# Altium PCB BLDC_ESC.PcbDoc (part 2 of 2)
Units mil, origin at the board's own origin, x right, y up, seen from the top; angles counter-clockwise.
Board outline 1574.8 x 2362.2 mil, 2 copper layers (Top Layer, Bottom Layer), stack 65.792 mil thick; 131 components, 100 nets, 479 pads, 292 vias.
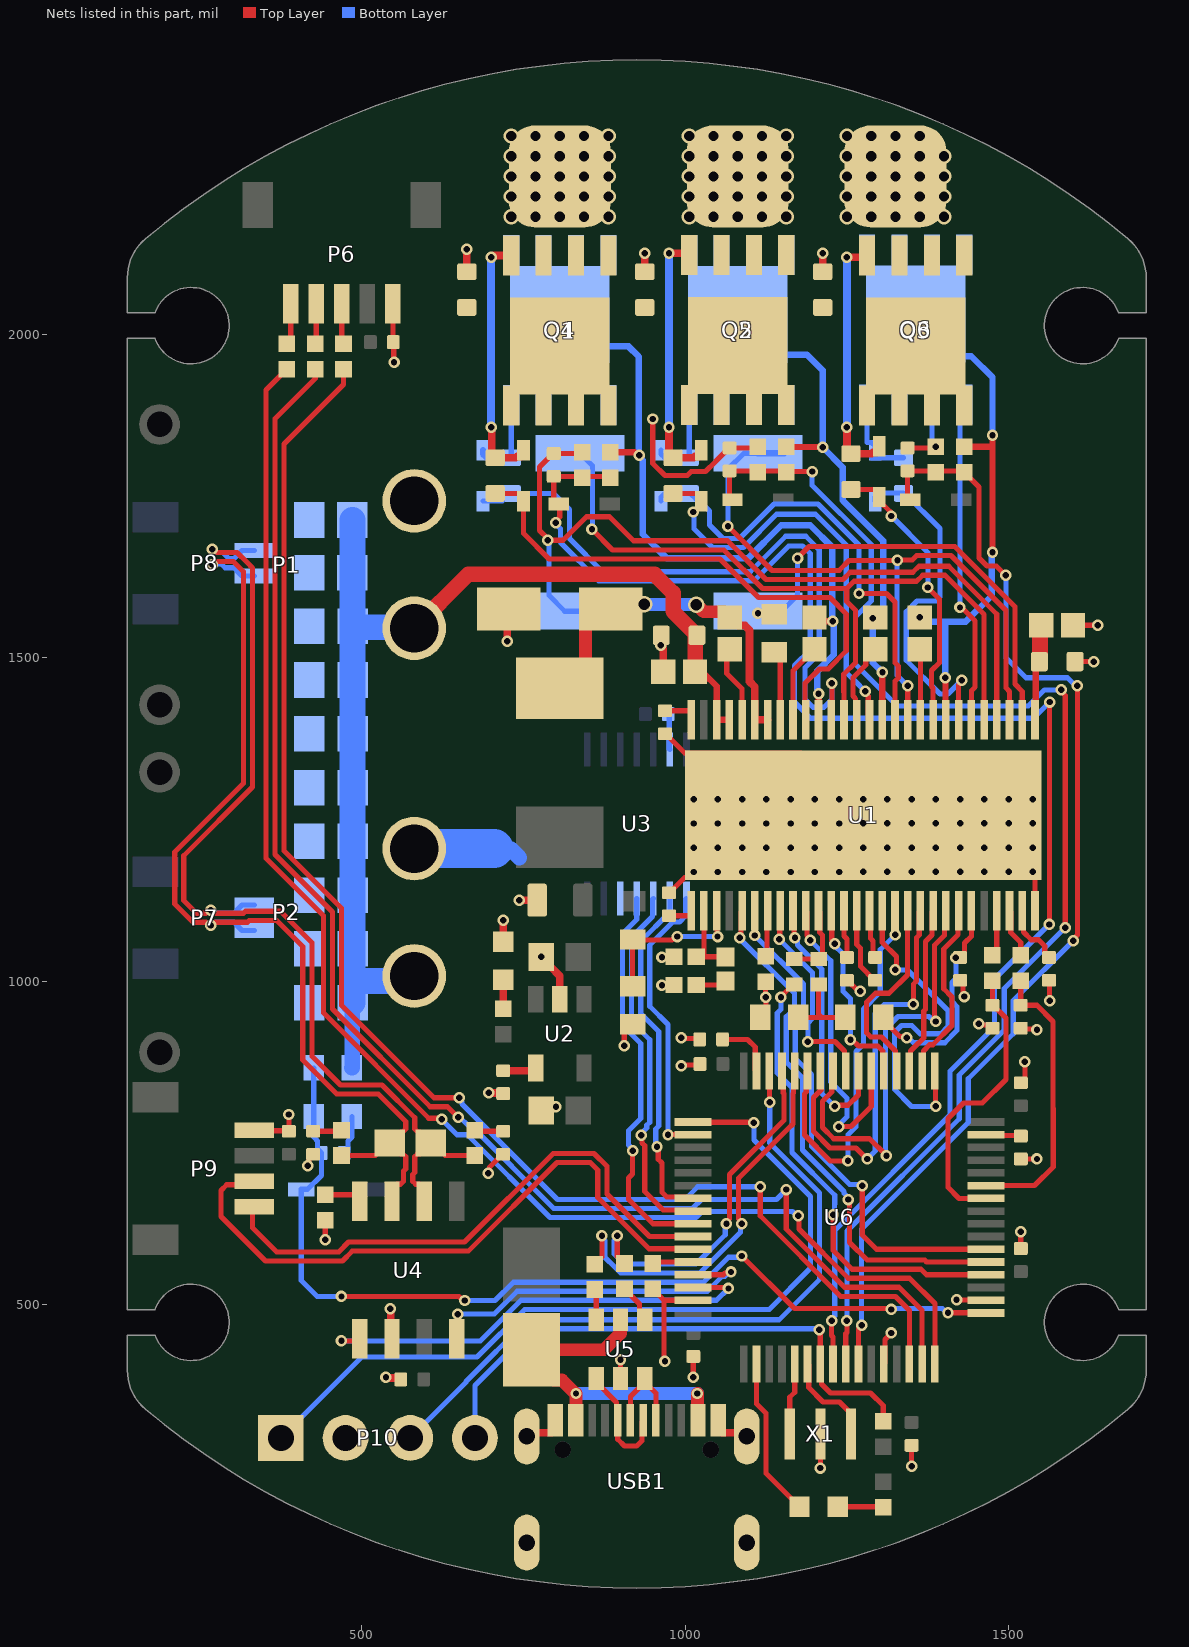
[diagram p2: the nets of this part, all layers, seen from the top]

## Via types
v1: diameter 17.72, hole 9.84, Top Layer to Bottom Layer, tented both sides, 211 vias
v2: diameter 23.62, hole 15.75, Top Layer to Bottom Layer, tented both sides, 74 vias
v3: diameter 25.59, hole 17.72, Top Layer to Bottom Layer, tented both sides, 7 vias

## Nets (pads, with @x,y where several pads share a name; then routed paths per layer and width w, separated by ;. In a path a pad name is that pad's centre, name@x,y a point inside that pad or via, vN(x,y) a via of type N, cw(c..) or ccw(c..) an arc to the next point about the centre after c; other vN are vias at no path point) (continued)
A_SENSE: C36.2 D9.2 R17.1 R25.2 U6.8 | length 2457.5
  Top Layer w8: v1(799.81,1708.56) 799.81,1711.19 806.14,1717.53 806.14,1735.74 D9.2@804.38,1737.5 802.69,1737.5 796.85,1743.34 C36.2@796.85,1780.07 882.38,1780.07 R17.1@884.35,1778.1 ; v1(1226.28,474.89) 1226.28,452.19 1228.44,450.03 U6.8@1228.44,408.19 ; v1(1562.5,1087.5) 1563.01,1088.01 1563.01,1430.74 v1(1563.51,1431.25)
  Bottom Layer w8: v1(799.81,1708.56) 799.81,1706.27 807.06,1699.02 807.06,1678.06 866.37,1618.75 1106.43,1618.75 1160.2,1672.52 1181.49,1672.52 1193.33,1660.68 1193.33,1512.08 1168.75,1487.5 1168.75,1431.25 1193.75,1406.25 1538.51,1406.25 v1(1563.51,1431.25) ; v1(1226.28,474.89) 1226.28,477.52 1231.14,482.38 1231.14,482.81 1231.25,482.92 1231.25,614.6 1409.5,792.85 1409.5,860.55 1478.25,929.3 1478.25,1003.25 v1(1562.5,1087.5)
B_SENSE: C37.2 D10.2 R18.1 R26.2 U6.9 | length 2060.6
  Top Layer w8: D10.2@1073.13,1743.75 1068.75,1748.13 C37.2@1068.75,1788.53 1154.28,1788.53 1155.32,1787.5 v1(1196.26,1787.5) ; U6.9@1248.12,408.19 1248.12,455.12 1250,457 v1(1250,474.89) ; v1(1581.25,1450) 1581.25,1447.37 1587.39,1441.23 v1(1587.39,1082.65)
  Bottom Layer w8: v1(1196.26,1787.5) 1196.26,1766.24 1287.5,1675 1287.5,1587.5 1263.05,1563.05 1263.05,1489.73 1327.78,1425 1530.2,1425 1555.31,1450.11 1581.14,1450.11 v1(1581.25,1450) ; v1(1250,474.89) 1250,613.55 1423.5,787.05 1423.5,854.75 1493.22,924.47 1493.22,988.37 1587.39,1082.55 v1(1587.39,1082.65)
BOOT0: R38.1 U6.60 | length 62.8
  Top Layer w8: R38.1@950,563.43 952.24,565.67 U6.60@1011.9,565.67
C_SENSE: C38.2 D11.2 R19.1 R27.2 U6.10 | length 1773.8
  Top Layer w8: U6.10@1267.81,408.19 1267.81,463.03 1272.75,467.98 v1(1272.75,468.2) ; D11.2@1348.13,1743.75 1343.75,1748.13 C38.2@1343.75,1788.53 1387.5,1788.53 1429.28,1788.53 1454.14,1763.67 1454.14,1653.86 1466.36,1641.64 1480.85,1641.64 1495.5,1626.99 v1(1495.69,1626.99) ; v1(1600,1062.5) 1600,1065.13 1606.25,1071.38 v1(1606.25,1456.25)
  Bottom Layer w8: v1(1272.75,468.2) 1272.75,616.5 1437.5,781.25 1437.5,848.95 1507.22,918.67 1507.22,969.72 v1(1600,1062.5) ; v1(1495.69,1626.99) 1495.69,1499.73 1526.56,1468.86 1591.01,1468.86 1603.62,1456.25 v1(1606.25,1456.25)
CAN1_N: P7.2 P8.2 R32.1 R33.1 U4.6 | length 1630.7
  Top Layer w8: v1(268.75,1667.47) 271.38,1667.47 276.24,1662.61 307.19,1662.61 323.05,1646.75 331.25,1638.55 331.25,1300 225,1193.75 225,1124.66 244.87,1104.79 259.19,1104.79 264.05,1109.65 v1(266.68,1109.65) 269.31,1109.65 274.16,1104.79 317.46,1104.79 320.41,1107.75 374.55,1107.75 423.01,1059.29 423.01,883.63 467.25,839.38 531.25,839.38 582,788.63 582,771.52 586.69,766.83 589.71,766.83 R32.1@606.54,750 ; U4.6@596.85,659.4 596.85,678.1 589.04,685.91 583.54,685.91 578.85,690.6 578.85,700.69 582,703.84 582,728.48 586.69,733.17 589.71,733.17 R32.1@606.54,750 ; R33.1@675,730.32 629.13,730.32 609.45,750 R32.1@606.54,750
  Bottom Layer w8: v1(266.68,1109.65) 269.31,1109.65 274.16,1104.79 285.41,1104.79 285.5,1104.88 302.61,1104.88 307.3,1109.57 307.3,1109.76 315.11,1117.57 P7.2@333.81,1117.57 ; v1(268.75,1667.47) 271.38,1667.47 276.24,1662.61 285.19,1662.61 294.93,1652.87 302.61,1652.87 307.3,1657.55 307.3,1657.74 315.11,1665.55 P8.2@333.81,1665.55
CAN1_P: P7.1 P8.1 R31.1 R32.2 U4.7 | length 1610.5
  Top Layer w8: v1(268.75,1643.75) 271.38,1643.75 276.24,1648.61 301.39,1648.61 317.25,1632.75 317.25,1305.8 211,1199.55 211,1118.86 239.07,1090.79 259.19,1090.79 264.05,1085.94 v1(266.68,1085.94) 269.31,1085.94 274.16,1090.79 323.25,1090.79 326.21,1093.75 368.75,1093.75 409.01,1053.49 409.01,877.83 413.11,873.73 461.45,825.38 525.45,825.38 568,782.83 568,771.52 563.31,766.83 560.29,766.83 R32.2@543.46,750 ; R31.1@468.75,730.32 520.87,730.32 540.55,750 R32.2@543.46,750 ; U4.7@546.85,659.4 546.85,678.1 554.66,685.91 560.16,685.91 564.85,690.6 564.85,706.49 568,709.64 568,728.48 563.31,733.17 560.29,733.17 R32.2@543.46,750
  Bottom Layer w8: v1(266.68,1085.94) 269.31,1085.94 274.16,1090.79 291.21,1090.79 291.3,1090.88 302.61,1090.88 307.3,1086.2 307.3,1086.01 315.11,1078.2 P7.1@333.81,1078.2 ; v1(268.75,1643.75) 269.75,1644.75 283.25,1644.75 289.13,1638.87 302.61,1638.87 307.3,1634.18 307.3,1633.99 315.11,1626.18 P8.1@333.81,1626.18
CAN1_RX: U4.4 U6.61 | length 549.1
  Top Layer w8: U4.4@646.85,446.8 648.43,448.38 v1(648.43,485.21) ; U6.61@1011.9,545.99 1059.08,545.99 1061.6,548.51 1068.93,548.51 v1(1070.79,550.37)
  Bottom Layer w8: v1(648.43,485.21) 705.01,485.21 740.3,520.5 1034.05,520.5 1057.22,543.67 1061.46,543.67 1068.16,550.37 v1(1070.79,550.37)
CAN1_TX: U4.1 U6.62 | length 716.7
  Top Layer w8: v1(468.75,443.75) 493.8,443.75 U4.1@496.85,446.8 ; U6.62@1011.9,526.3 1065.39,526.3 v1(1066.89,524.81)
  Bottom Layer w8: v1(468.75,443.75) 683.35,443.75 746.1,506.5 1048.58,506.5 v1(1066.89,524.81)
DC_CAL: U1.12 U6.37 | length 300.3
  Top Layer w8: U1.12@1225.79,1108.61 1226.61,1107.79 1226.61,1063.66 1230.96,1059.31 v1(1230.96,1057.49) ; v1(1255.45,909.21) 1258.07,909.21 1267.78,899.5 1297.53,899.5 1305.27,891.76 1305.27,862.86 U6.37@1307.18,860.95
  Bottom Layer w8: v1(1230.96,1057.49) 1230.96,1054.86 1243.75,1042.07 1243.75,984.22 1255.45,972.53 v1(1255.45,909.21)
EN_GATE: U1.16 U6.33 | length 548.9
  Top Layer w8: U1.16@1304.53,1108.61 1304.53,1059.77 1326.55,1037.75 ; v1(1324.67,1017.26) 1326.53,1019.12 1326.53,1037.72 ; U6.33@1385.92,860.95 1386.71,860.16 1386.71,807.04 v1(1387.5,806.25)
  Bottom Layer w8: v1(1324.67,1017.26) 1343.57,1017.26 1406.36,954.47 1406.36,929.69 1395.31,918.64 1363.04,918.64 1350.32,931.36 1334.59,931.36 1323.54,920.31 1323.54,832.71 1350,806.25 v1(1387.5,806.25)
GAIN: U1.10 U6.38 | length 482.8
  Top Layer w8: U1.10@1186.42,1108.61 1188.32,1106.71 1188.32,1070.56 1193.25,1065.64 v1(1193.25,1063.01) ; v1(1237.5,775) 1256.25,775 1287.49,806.24 U6.38@1287.49,860.95
  Bottom Layer w8: v1(1193.25,1063.01) 1225,1031.25 1225,843.75 1250,818.75 1250,790.13 1237.5,777.63 v1(1237.5,775)
GH_A: D3.1 R14.1 U1.47 | length 851.1
  Top Layer w8: R14.1@706.25,1753.69 744.09,1753.69 750,1747.79 D3.1@750,1741.88 750,1692.08 789.62,1652.46 1053.79,1652.46 1113.47,1592.78 1176.3,1592.78 ; 1176.33,1592.81 1223.67,1592.81 1249.05,1567.43 1249.05,1510.4 1221.18,1482.53 1207.53,1482.53 1185.24,1460.24 1185.24,1405.06 U1.47@1186.42,1403.89
GH_B: D4.1 R15.1 U1.42 | length 674.7
  Top Layer w8: R15.1@981.25,1753.69 1019.09,1753.69 1025,1747.79 1025,1735.97 1014.03,1725 v1(1012.5,1725) ; v1(1278.33,1447.77) 1278.33,1445.15 1282.94,1440.54 1282.94,1405.79 U1.42@1284.84,1403.89
  Bottom Layer w8: v1(1012.5,1725) 1013.43,1724.07 1013.43,1699.07 1042.31,1670.19 1089.99,1670.19 1141.3,1721.5 1201.4,1721.5 1249.05,1673.85 1249.05,1477.06 1263.33,1462.78 v1(1278.33,1447.77)
GH_C: D5.1 R16.1 U1.37 | length 441.5
  Top Layer w8: R16.1@1256.25,1759.94 1294.09,1759.94 1300,1754.04 1300,1742.22 1316.89,1725.33 1316.89,1720.61 v1(1318.75,1718.75) ; v1(1374.89,1608.36) 1393.2,1590.05 1393.2,1492.05 1380.92,1479.77 1380.92,1455.08 1383.27,1452.74 U1.37@1383.27,1403.89
  Bottom Layer w8: v1(1318.75,1718.75) 1375.46,1662.04 1375.46,1608.92 v1(1374.89,1608.36)
GL_A: D6.1 R20.1 U1.45 | length 988
  Top Layer w8: U1.45@1225.79,1403.89 1226.96,1405.06 1226.96,1459.54 v1(1226.29,1460.21)
  Bottom Layer w8: D6.1@687.5,1741.88 R20.1@717.48,1741.88 ; R20.1@731.25,1753.69 796.31,1753.69 821.06,1728.94 821.06,1683.86 872.17,1632.75 1100.63,1632.75 1155.38,1687.5 1186.31,1687.5 1207.33,1666.48 1207.33,1506.26 1185.24,1484.17 1185.24,1435.47 1197.46,1423.25 1214.74,1423.25 1226.96,1435.47 1226.96,1459.54 v1(1226.29,1460.21)
GL_B: D7.1 R21.1 U1.40 | length 726.8
  Top Layer w8: v1(1268.64,1599.04) 1311.19,1599.04 1324.45,1585.78 1324.45,1492.05 1329.44,1487.06 1329.44,1468.61 1324.21,1463.38 U1.40@1324.21,1403.89
  Bottom Layer w8: D7.1@962.5,1741.88 962.5,1747.79 968.41,1753.69 1008.21,1753.69 1017.21,1744.69 1019.48,1744.69 1037.5,1726.67 1037.5,1705.03 1058.34,1684.19 1084.19,1684.19 1137.5,1737.5 1205.2,1737.5 1268.64,1674.06 v1(1268.64,1599.04)
GL_C: D8.1 R22.1 U1.35 | length 552.6
  Top Layer w8: U1.35@1422.64,1403.89 1422.64,1457.51 1427.29,1462.16 v1(1427.29,1464.79)
  Bottom Layer w8: D8.1@1293.75,1741.88 1293.75,1747.79 1300.45,1754.48 1336.71,1754.48 R22.1@1337.5,1753.69 1339.46,1753.69 1393.75,1699.4 1393.75,1593.54 1387.71,1587.5 1358.4,1587.5 1341.64,1570.75 1341.64,1495.86 1393.75,1443.75 1406.25,1443.75 v1(1427.29,1464.79)
GND: C1.1 C2.1 C3.2 C4.2 C5.2 C8.2 C10.2 C13.2 C14.2 C15.2 C16.2 C17.2 C18.2 C19.1 C20.1 C21.1 C22.1 C23.1 C24.1 C25.1 C26.1 C27.1 C28.1 C29.1 C30.1 C31.1 C32.1 C33.2 C34.2 C35.2 C36.1 C37.1 C38.1 C39.1 C40.1 C41.1 C42.1 C43.1 C44.1 C45.1 C46.1 C47.1 C48.1 C49.1 C50.1 C51.1 D1.2 DS1.2 P1.2 P2.2 P6.1 P9.1 P10.2 Q6.1 Q6.2 Q6.3 R3.1 R4.1 R5.2 R6.2 R8.1 R13.2 R23.2 R24.2 R25.1 R26.1 R27.1 R34.1 R38.2 U1.28 U1.30 U1.32 U1.34 U1.EXP U2.2 U3.5 U3.13 U4.2 U5.2 U6.12 U6.18 U6.63 USB1.1 USB1.12 USB1.A USB1.B USB1.C USB1.D X1.2 | length 5943.8
  Top Layer w8: P9.1@333.81,769.29 334.6,768.5 386.71,768.5 C44.1@387.5,767.72 v1(387.5,793.75) ; v1(416.46,714.79) 418.32,716.65 418.32,726.44 424.17,732.28 C41.1@425,732.28 ; v1(443.75,600.11) R34.1@443.75,630.32 ; P6.1@547.83,2046.9 548.4,2046.33 548.4,1988.07 C39.1@548.97,1987.5 549.48,1986.98 549.48,1956.77 v1(550,1956.25) ; v1(695.75,703.08) 697.61,704.94 697.61,712.13 717.77,732.28 C42.1@718.75,732.28 ; R25.1@840.6,1817.47 838.63,1815.5 C36.1@796.85,1815.5 795.87,1815.5 775,1794.64 775,1696.38 787.5,1683.88 v1(787.5,1681.25) 810.99,1681.25 847.39,1717.66 883.03,1717.66 920.22,1680.46 1065.38,1680.46 1125.07,1620.78 1164.7,1620.78 ; U5.2@900,385.97 v1(900,414.64) ; v1(905.73,900) 905.73,921.22 906.65,922.15 907.92,922.15 R4.1@918.75,932.97 ; R38.2@950,524.06 967.44,506.62 ; v1(950,1868.75) 950,1799.86 968.61,1781.25 1003.12,1781.25 1009.38,1787.5 1031.61,1787.5 1046.77,1802.66 1046.77,1802.97 1067.77,1823.97 C37.1@1068.75,1823.97 1110.53,1823.97 R26.1@1112.5,1825.93 ; v1(964.11,993.75) C2.1@982.68,993.75 ; v1(964.11,1037.05) 982.22,1037.05 C1.1@982.68,1037.5 ; v1(968.75,412.5) 967.44,413.81 967.44,506.62 ; C3.2@968.75,1382.28 969.73,1382.28 999.37,1352.64 1178.61,1352.64 U1.EXP@1275,1256.25 1178.61,1159.86 1087.96,1159.86 999.37,1159.86 975.98,1136.47 R3.1@975,1136.47 ; v1(993.75,868.75) 995.3,870.3 1021.33,870.3 C47.1@1022.88,871.85 ; v1(993.75,912.5) 995.09,911.16 1021.02,911.16 C46.1@1022.37,909.82 ; U6.63@1011.9,506.62 967.44,506.62 ; v1(1012.5,387.5) C45.1@1012.5,419.78 ; v1(1112.5,1568.75) 1135.78,1568.75 R6.2@1137.5,1567.03 ; R8.1@1115.94,943.75 1125,952.81 v1@1125,975 ; v1(1124.32,974.99) 1124.32,998.68 R5.2@1124.85,999.21 ; 1164.73,1620.81 1243.94,1620.81 1255.03,1631.9 1305.6,1631.9 1305.68,1631.82 1351.89,1631.82 1361.28,1641.21 1407.39,1641.21 1481.69,1566.91 U1.32@1481.69,1403.89 ; v1(1173.68,1653.67) 1191.56,1671.55 1416.66,1671.55 1509.69,1578.51 1509.69,1459.06 1521.06,1447.69 U1.30@1521.06,1403.89 ; v1(1209.02,247.23) X1.2@1209.01,300 ; C10.2@1250,1001.03 1250.98,1001.03 1267.82,984.19 v1(1270.45,984.19) ; v1(1275,1243.75) v1(1312.5,1243.75) v1(1350,1243.75) v1(1387.5,1243.75) v1(1425,1243.75) U1.EXP@1444.35,1243.75 ; U6.12@1307.18,408.19 1309.08,410.1 1309.08,446.09 1318.47,455.48 v1(1318.47,456.05) ; C38.1@1343.75,1823.97 1385.53,1823.97 v1(1387.5,1825.93) ; v1(1350,250) C48.1@1350,282.28 ; v1(1419.41,507.23) 1419.71,506.93 1464.35,506.93 U6.18@1464.66,506.62 ; v1(1424.71,1577.43) 1427.34,1577.43 1448.01,1556.76 1448.01,1454.26 1442.32,1448.57 U1.34@1442.32,1403.89 ; C13.2@1425,1001.03 1429.39,996.65 1429.39,977.91 v1(1431.25,976.05) ; U1.EXP@1444.35,1256.25 1497.18,1203.43 1540.75,1159.86 U1.28@1540.75,1108.61 ; v1(1454.03,934.1) 1455.89,932.24 1469.85,932.24 C17.2@1474.9,927.18 ; C18.2@1518.65,927.18 1519.74,926.09 1542.66,926.09 v1(1543.75,925) ; C51.1@1518.75,586.47 v1(1518.75,612.5) ; C49.1@1518.75,725 v1(1543.75,725) ; C50.1@1518.75,842.72 1519.27,842.72 1525.11,848.56 v1(1525.11,875) ; C14.2@1562.5,1001.03 1562.92,1000.62 1562.92,970 v1(1563.33,969.58) ; C15.2@1599.61,1550 v1(1637.5,1550) ; C16.2@1602.56,1493.75 v1(1631.25,1493.75)
  Top Layer w12: v1(537.5,387.5) 538.59,386.41 558.33,386.41 C43.1@560.38,384.35 ; v1(543.86,493.64) 544.84,492.66 544.84,448.81 U4.2@546.85,446.8 ; C33.2@662.5,2096.31 v1(662.5,2131.25) ; v1(696.55,827.62) 697.35,826.83 717.96,826.83 C32.1@718.75,826.03 ; DS1.2@718.75,1060.78 v1@718.75,1093.75 ; v1(725,1525) 725,1572.49 D1.2@727.51,1575 ; v1(743.75,1125) C8.2@771.21,1125 ; USB1.A@755.12,296.16 760.92,301.96 793.41,301.96 799.22,307.77 USB1.1@799.22,320.96 ; C30.1@777.71,800 783.35,805.64 v1(800.25,805.64) ; C29.1@777.71,1035.53 791.39,1021.85 792.14,1021.85 806.25,1007.73 U2.2@806.25,971.9 ; C34.2@937.5,2096.31 v1(937.5,2125) ; v1(962.5,1518.75) 962.5,1517.2 965.99,1513.71 C4.2@965.99,1478.1 ; C5.2@963.04,1534.35 962.77,1534.08 962.77,1520.03 v1@965.14,1517.66 ; USB1.12@1051.18,320.96 1051.18,307.77 1056.99,301.96 1089.48,301.96 USB1.D@1095.28,296.16 ; C35.2@1212.5,2096.31 v1(1212.5,2125)
  Bottom Layer w8: C31.1@473.08,734.4 478.92,740.24 478.92,753 484.89,758.96 R13.2@484.89,790.65 ; v1(787.5,1681.25) 789.36,1679.39 789.36,1596.25 813.9,1571.7 R23.2@837.5,1571.7 ; C40.1@973.97,1412.5 975.26,1411.21 975.26,1359.03 U3.13@976.38,1357.91 ; R24.2@1112.5,1571.7 1149.14,1571.7 1173.68,1596.25 v1(1173.68,1653.67) ; Q6.2@1381.25,1891.1 1381.25,1834.81 1387.5,1828.56 v1(1387.5,1825.93) ; v1(1424.71,1577.43) 1424.71,1884.56 Q6.1@1431.25,1891.1
  Bottom Layer w24: 729.69,1204.68 743.75,1190.62
  Bottom Layer w60: P2.2@581.25,1204.68 704.68,1204.68
  other v1: 777.71,1037.5 718.75,1093.75 1012.96,1168.49 1050.46,1168.49 1087.96,1168.49 1125.46,1168.49 1162.96,1168.49 1200.46,1168.49 1237.96,1168.49 1275,1168.75 1312.5,1168.75 1350,1168.75 1387.5,1168.75 1425,1168.75 1462.5,1168.75 1500,1168.75 1537.5,1168.75 1012.96,1205.99 1050.46,1205.99 1087.96,1205.99 1125.46,1205.99 1162.96,1205.99 1200.46,1205.99 1237.96,1205.99 1275,1206.25 1312.5,1206.25 1350,1206.25 1387.5,1206.25 1425,1206.25 1462.5,1206.25 1500,1206.25 1537.5,1206.25 1012.96,1243.49 1050.46,1243.49 1087.96,1243.49 1125.46,1243.49 1162.96,1243.49 1200.46,1243.49 1237.96,1243.49 1462.5,1243.75 1500,1243.75 1537.5,1243.75 1012.96,1280.99 1050.46,1280.99 1087.96,1280.99 1125.46,1280.99 1162.96,1280.99 1200.46,1280.99 1237.96,1280.99 1275,1281.25 1312.5,1281.25 1350,1281.25 1387.5,1281.25 1425,1281.25 1462.5,1281.25 1500,1281.25 1537.5,1281.25
HAL_A: R28.2 U6.14 | length 2259.8
  Top Layer w8: R28.2@471.9,1945.96 471.9,1921.9 380,1830 380,1201.25 468.75,1112.5 468.75,962.5 611.67,819.58 v1(650.83,819.58) ; v1(1115.98,682.01) 1115.98,637.13 1240.49,512.61 1324.92,512.61 1346.55,490.99 U6.14@1346.55,408.19
  Bottom Layer w8: v1(650.83,819.58) 650.83,816.96 654.92,812.87 654.92,810.18 802.6,662.5 1000,662.5 1019.51,682.01 v1(1115.98,682.01)
HAL_B: R29.2 U6.15 | length 2299.1
  Top Layer w8: R29.2@428.15,1945.96 428.15,1931.25 366,1869.1 366,1195.45 454.75,1106.7 454.75,956.7 605.87,805.58 632.84,805.58 v1(649.05,789.38) ; v1(1156.25,677.74) 1156.14,677.64 1156.14,616.76 1246.29,526.61 1330.72,526.61 1366.23,491.1 U6.15@1366.23,408.19
  Bottom Layer w8: v1(649.05,789.38) 651.68,789.38 664.56,776.5 668.8,776.5 796.8,648.5 1011,648.5 1025,662.5 1141.01,662.5 v1(1156.25,677.74)
HAL_C: R30.2 U6.16 | length 2289.3
  Top Layer w8: R30.2@384.4,1945.96 352,1913.56 352,1189.65 440.75,1100.9 440.75,950.9 603.65,788 621.78,788 v1(623.64,786.14) ; v1(1175,637.5) 1176.06,636.44 1176.06,616.64 1252.09,540.61 1346.89,540.61 1385.92,501.58 U6.16@1385.92,408.19
  Bottom Layer w8: v1(623.64,786.14) 647.28,762.5 663,762.5 791,634.5 1016.8,634.5 1026.16,643.86 1166.01,643.86 1172.37,637.5 v1(1175,637.5)
INH_A: U1.17 U6.43 | length 601.9
  Top Layer w8: U6.43@1189.07,860.95 1187.16,859.05 1187.16,828.54 1184.28,825.66 1184.28,761.95 1224.25,721.99 v1(1251.57,721.99) ; U1.17@1324.21,1108.61 1324.44,1108.38 1324.44,1071.75 v1(1324.67,1071.52)
  Bottom Layer w8: v1(1251.57,721.99) 1251.57,762.4 1264,774.83 1264,891.09 1275.75,902.84 1275.75,957 1301.43,982.68 1301.43,1048.28 v1(1324.67,1071.52)
INH_B: U1.19 U6.42 | length 643.7
  Top Layer w8: U6.42@1208.75,860.95 1210.65,859.05 1210.65,832.23 1198.28,819.86 1198.28,767.75 1223.89,742.14 1264.11,742.14 v1(1281.25,725) ; v1(1352.67,964.22) 1352.67,995.05 1357.53,999.91 1357.53,1066.92 1361.68,1071.07 1361.68,1106.71 U1.19@1363.58,1108.61
  Bottom Layer w8: v1(1281.25,725) 1293.75,737.5 1293.75,950 1307.59,963.84 1352.3,963.84 v1(1352.67,964.22)
INH_C: U1.21 U6.41 | length 675.9
  Top Layer w8: U6.41@1228.44,860.95 1226.53,859.05 1226.53,828.31 1212.28,814.06 1212.28,773.55 1229.69,756.14 1285.07,756.14 v1(1311.1,730.11) ; v1(1387.5,937.5) 1387.5,940.13 1385.53,942.1 1385.53,1055.33 1401.05,1070.85 1401.05,1106.71 U1.21@1402.95,1108.61
  Bottom Layer w8: v1(1311.1,730.11) 1309.54,731.67 1309.54,926.11 1328.79,945.36 1377.01,945.36 1384.87,937.5 v1(1387.5,937.5)
INL_A: U1.18 U6.36 | length 315.1
  Top Layer w8: U6.36@1326.86,860.95 1324.95,862.86 1324.95,891.88 1303.33,913.5 1286.93,913.5 1280.5,919.92 1280.5,967.58 1294.12,981.19 1315.27,981.19 1343.53,1009.45 1343.53,1108.24 U1.18@1343.9,1108.61
INL_B: U1.20 U6.35 | length 262.9
  Top Layer w8: U6.35@1346.55,860.95 1348.45,862.86 1348.45,891.88 1356.01,899.44 1368.64,912.07 1368.64,953.52 1371.53,956.41 1371.53,1061.12 1381.36,1070.96 1381.36,1106.71 U1.20@1383.27,1108.61
INL_C: U1.22 U6.34 | length 284.5
  Top Layer w8: U6.34@1366.23,860.95 1368.13,862.86 1368.13,891.76 1377.87,901.5 1382.75,901.5 1412.39,931.14 1412.39,975.11 1399.53,987.97 1399.53,1049.53 1421.93,1071.93 1421.93,1107.91 U1.22@1422.64,1108.61
LED: DS2.2 U6.2 | length 248.2
  Top Layer w8: U6.2@1110.33,408.19 1110.33,346.71 1124.96,332.08 1124.96,239.26 DS2.2@1176.72,187.5
M_OC: U1.9 U6.39 | length 410
  Top Layer w8: U1.9@1166.73,1108.61 1168.22,1107.13 1168.22,1068.23 v1(1169.71,1066.75) ; v1(1231.14,806.25) 1233,808.11 1251.86,808.11 1267.81,824.06 U6.39@1267.81,860.95
  Bottom Layer w8: v1(1169.71,1066.75) 1169.71,1064.12 1173.75,1060.08 1173.75,1055.84 1211,1018.58 1211,826.39 v1(1231.14,806.25)
M_PWM: U1.8 U6.40 | length 321.3
  Top Layer w8: v1(1145.25,1064.67) 1146.15,1065.57 1146.15,1107.72 U1.8@1147.05,1108.61 ; v1(1189.73,906.34) 1231.64,906.34 1246.21,891.77 1246.21,862.86 U6.40@1248.12,860.95
  Bottom Layer w8: v1@1145.25,1064.53 1196.85,1012.94 1196.85,942.39 1189.73,935.27 v1(1189.73,906.34)
NetC1_2: C1.2 R1.2 U1.2 | length 118.5
  Top Layer w8: C1.2@1017.32,1037.5 C1.2@1023.57,1037.5 ; U1.2@1028.94,1108.61 1028.94,1042.86 C1.2@1023.57,1037.5 ; R1.2@1062.5,1037.45 R1.2@1062.5,1037.45 C1.2@1023.57,1037.5
NetC2_2: C2.2 R1.1 | length 47.8
  Top Layer w8: C2.2@1017.32,993.75 1056.2,993.75 R1.1@1062.5,1000.05
NetC3_1: C3.1 U1.56 | length 53.2
  Top Layer w8: C3.1@968.75,1417.72 1007.35,1417.72 1009.25,1415.81 U1.56@1009.25,1403.89
NetC6_1: C6.1 U1.52 | length 120.7
  Top Layer w8: C6.1@1068.75,1512.89 1064.31,1508.45 1064.31,1475.57 1087.99,1451.88 U1.52@1087.99,1403.89
NetC6_2: C6.2 D1.1 L1.1 U1.50 U1.51 | length 561.5
  Top Layer w12: C6.2@1068.75,1562.11 1081.45,1549.41 1092.42,1549.41 1099.45,1542.38 1099.45,1463.05 1107.68,1454.82 U1.51@1107.68,1403.89 U1.50@1127.36,1403.89
  Top Layer w20: L1.1@806.25,1452.5 810,1456.25 812.03,1456.25 845.78,1490 845.78,1551.54 869.24,1575 D1.1@884.99,1575 892.68,1582.69 v3(936.82,1582.69) ; v3(1017.25,1581.64) 1017.99,1581.64 1028.82,1570.81 1060.05,1570.81 C6.2@1068.75,1562.11
  Bottom Layer w20: v3(936.82,1582.69) 937.35,1582.16 1016.72,1582.16 v3(1017.25,1581.64)
NetC7_1: C7.1 U1.48 | length 122.8
  Top Layer w8: U1.48@1166.73,1403.89 1166.73,1479.63 C7.1@1200,1512.89
NetC9_1: C9.1 U1.43 | length 125.6
  Top Layer w8: U1.43@1265.16,1403.89 1263.25,1405.79 1263.25,1436.18 1261.38,1438.06 1261.38,1438.54 1259.47,1440.45 1259.47,1468.74 1279.05,1488.32 1279.05,1498.19 C9.1@1293.75,1512.89
NetC10_1: C10.1 U1.13 | length 74
  Top Layer w8: U1.13@1245.47,1108.61 1245.47,1069.65 1250,1065.12 C10.1@1250,1036.47
NetC11_1: C11.1 U1.14 | length 120
  Top Layer w8: U1.14@1265.16,1108.61 1265.16,1056.32 1270.83,1050.65 1270.83,1022.97 1292.77,1001.03 C11.1@1293.75,1001.03
NetC11_2: C11.2 U1.15 | length 75.8
  Top Layer w8: U1.15@1284.84,1108.61 1286.35,1107.1 1286.35,1066.1 1290.53,1061.93 1290.53,1039.69 C11.2@1293.75,1036.47
NetC12_1: C12.1 U1.38 | length 109.5
  Top Layer w8: C12.1@1362.5,1512.89 1363.58,1511.81 U1.38@1363.58,1403.89
NetC13_1: C13.1 R7.2 U1.23 | length 345.1
  Top Layer w8: R7.2@1306.25,943.75 1306.25,939.81 1331.79,914.27 1340.63,914.27 v1(1342.41,912.5) ; v1(1418.38,1035.84) 1424.37,1035.84 C13.1@1425,1036.47 1425.98,1036.47 1431.83,1042.31 1431.83,1058.87 1442.32,1069.37 U1.23@1442.32,1108.61
  Bottom Layer w8: v1(1342.41,912.5) 1344.86,912.5 1352.72,904.64 1401.11,904.64 1420.36,923.89 1420.36,960.27 1412.39,968.24 1412.39,997.73 1418.38,1003.72 v1(1418.38,1035.84)
NetC14_1: C14.1 U1.27 | length 96.4
  Top Layer w8: U1.27@1521.06,1108.61 1522.97,1106.71 1522.97,1075.83 1534.95,1063.85 1546.14,1063.85 1555.67,1054.32 1555.67,1042.31 1561.52,1036.47 C14.1@1562.5,1036.47
NetC32_2: C32.2 U2.4 | length 51.8
  Top Layer w12: C32.2@718.75,861.47 764.71,861.47 U2.4@768.85,865.6
NetC41_2: C41.2 R31.2 | length 44.6
  Top Layer w8: C41.2@425,767.72 466.78,767.72 R31.2@468.75,769.69
NetC42_2: C42.2 R33.2 | length 44.6
  Top Layer w8: R33.2@675,769.69 676.97,767.72 C42.2@718.75,767.72
NetC46_2: C46.2 U6.47 | length 93.3
  Top Layer w8: C46.2@1057.8,909.82 1096.43,909.82 1108.42,897.83 1108.42,862.86 U6.47@1110.33,860.95
NetC49_2: C49.2 U6.31 | length 55
  Top Layer w8: U6.31@1464.66,762.52 1465.7,761.48 1517.7,761.48 C49.2@1518.75,760.43
NetD3_2: D3.2 Q1.4 R14.2 | length 397
  Top Layer w12: v1(700,1856.25) 701.09,1855.16 701.09,1813.97 R14.2@706.25,1808.81 738.19,1808.81 740.25,1810.87 746.16,1810.87 750,1814.71 D3.2@750,1820.62 ; v1(700,2118.75) 701.55,2118.75 704.2,2121.4 Q1.4@731.25,2121.4
  Bottom Layer w12: v1(700,1856.25) v1(700,2118.75)
NetD4_2: D4.2 Q2.4 R15.2 | length 403.3
  Top Layer w12: v1(975,1856.25) 975,1815.06 R15.2@981.25,1808.81 1013.19,1808.81 1015.25,1810.87 1021.16,1810.87 1025,1814.71 D4.2@1025,1820.62 ; v1(975,2125) 1003.44,2125 Q2.4@1006.25,2122.19
  Bottom Layer w12: v1(975,1856.25) v1(975,2125)
NetD5_2: D5.2 Q3.4 R16.2 | length 390.7
  Top Layer w12: v1(1250,1856.25) 1250,1821.31 R16.2@1256.25,1815.06 1288.19,1815.06 1290.25,1817.12 1296.16,1817.12 1300,1820.96 D5.2@1300,1826.87 ; v1(1250,2118.75) 1278.6,2118.75 Q3.4@1281.25,2121.4
  Bottom Layer w12: v1(1250,1856.25) v1(1250,2118.75)
NetD6_2: D6.2 Q4.4 R20.2 | length 133.6
  Bottom Layer w8: R20.2@731.25,1808.81 Q4.4@731.25,1890.31
  Bottom Layer w10: D6.2@687.5,1820.62 687.5,1814.71 692.34,1809.87 730.19,1809.87 R20.2@731.25,1808.81
NetD7_2: D7.2 Q5.4 R21.2 | length 133.6
  Bottom Layer w8: D7.2@962.5,1820.62 962.5,1814.71 968.34,1808.87 974.25,1808.87 974.31,1808.81 R21.2@1006.25,1808.81 Q5.4@1006.25,1890.31
NetD8_2: D8.2 Q6.4 R22.2 | length 143.1
  Bottom Layer w8: Q6.4@1281.25,1891.1 1281.25,1832.78 1281.66,1832.37 1287.91,1832.37 1293.75,1826.53 D8.2@1293.75,1820.62 1287.88,1814.75 1287.88,1808.87 1337.44,1808.87 R22.2@1337.5,1808.81
NetDS1_1: DS1.1 R11.2 | length 44.5
  Top Layer w12: R11.2@718.75,957.19 DS1.1@718.75,1001.73
NetDS2_1: DS2.1 R39.2 | length 70.9
  Top Layer w8: DS2.1@1235.78,187.5 1305.31,187.5 R39.2@1306.25,186.56
NetJ1_2: J1.2 J2.2 U1.11 | length 116.9
  Top Layer w8: J1.2@1168.75,1034.15 J2.2@1206.25,1034.15 1212.11,1040.01 1212.11,1070.82 1208.01,1074.91 1208.01,1106.71 U1.11@1206.1,1108.61
NetJ2_1: J2.1 R7.1 R8.2 | length 125.2
  Top Layer w8: R8.2@1175,943.75 1211.1,943.75 ; J2.1@1206.25,994.78 1206.25,948.6 1211.1,943.75 ; R7.1@1247.19,943.75 1211.1,943.75
NetP6_3: P6.3 R28.1 | length 62.7
  Top Layer w8: P6.3@469.09,2046.9 469.09,1988.14 R28.1@471.9,1985.33
NetP6_4: P6.4 R29.1 | length 62.2
  Top Layer w8: R29.1@428.15,1985.33 429.72,1986.91 P6.4@429.72,2046.9
NetP6_5: P6.5 R30.1 | length 64
  Top Layer w8: R30.1@384.4,1985.33 390.35,1991.29 P6.5@390.35,2046.9
NetR2_1: R2.1 R4.2 U1.3 | length 246.4
  Top Layer w8: R4.2@918.75,992.03 R2.1@918.75,1064.22 919.57,1063.4 979.52,1063.4 984.87,1068.75 v1(987.5,1068.75) ; U1.3@1048.62,1108.61 1049.31,1107.92 1049.31,1069.44 v1(1050,1068.75)
  Bottom Layer w8: v1(987.5,1068.75) v1(1050,1068.75)
NetR3_2: R3.2 U1.1 | length 40.7
  Top Layer w8: R3.2@975,1101.03 1007.35,1101.03 1009.25,1102.94 U1.1@1009.25,1108.61
NetR5_1: R5.1 U1.7 | length 71.1
  Top Layer w8: R5.1@1124.85,1038.59 1126.24,1039.97 1126.24,1062.51 1126.4,1062.67 1126.4,1107.65 U1.7@1127.36,1108.61
NetR6_1: R6.1 U1.49 | length 108
  Top Layer w8: R6.1@1137.5,1507.97 1147.05,1498.43 U1.49@1147.05,1403.89
NetR9_1: R9.1 U1.25 | length 71.8
  Top Layer w8: R9.1@1474.9,1039.59 1481.69,1046.38 U1.25@1481.69,1108.61
NetR10_1: R10.1 U1.26 | length 76.2
  Top Layer w8: U1.26@1501.38,1108.61 1503.28,1106.71 1503.28,1075.06 1518.65,1059.69 R10.1@1518.65,1039.59
NetR34_2: R34.2 U4.8 | length 58.8
  Top Layer w8: R34.2@443.75,669.69 489.04,669.69 496.85,661.87 U4.8@496.85,659.4
NetR35_2: R35.2 U5.4 | length 60.4
  Top Layer w8: R35.2@906.25,524.06 929.59,500.72 929.59,484.34 U5.4@937.4,476.53
NetR36_2: R36.2 U5.6 | length 47.7
  Top Layer w8: R36.2@860.14,523.23 862.6,520.77 U5.6@862.6,476.53
NetU5_1: U5.1 USB1.5 USB1.7 | length 185.4
  Top Layer w8: U5.1@862.6,385.97 862.6,380.06 878.19,364.48 878.19,364.11 893.76,348.54 893.76,322.87 USB1.5@895.67,320.96 895.67,291.83 906.25,281.25 925,281.25 933.13,289.38 933.13,319.06 USB1.7@935.04,320.96
NetU5_3: U5.3 USB1.6 USB1.8 | length 146.3
  Top Layer w8: USB1.6@915.36,320.96 915.36,357.66 929.59,371.89 929.59,378.16 U5.3@937.4,385.97 937.4,380.06 954.73,362.74 USB1.8@954.73,320.96
nFAULT: U1.6 U6.22 | length 790.7
  Top Layer w8: v1(1107.54,1070.48) 1107.61,1070.55 1107.61,1108.54 U1.6@1107.68,1108.61 ; v1(1273.67,683.68) 1273.67,607.58 1295.89,585.36 U6.22@1464.66,585.36
  Bottom Layer w8: v1(1107.54,1070.48) 1182.75,995.27 1182.75,951.5 1170.25,939 1170.25,880.8 1195.25,855.8 1195.25,744.61 1254.32,685.54 1271.81,685.54 v1(1273.67,683.68)
nOCTW: U1.5 U6.21 | length 818.2
  Top Layer w8: v1(1084.08,1066.99) 1084.08,1069.62 1086.09,1071.63 1086.09,1106.71 U1.5@1087.99,1108.61 ; v1(1252.27,662.29) 1254.11,660.46 1254.11,595.89 1281.39,568.61 1370.18,568.61 1373.11,565.67 1393.2,565.67 U6.21@1464.66,565.67
  Bottom Layer w8: v1(1084.08,1066.99) 1084.08,1065.85 1168.75,981.18 1168.75,957.3 1156.25,944.8 1156.25,875 1181.25,850 1181.25,738.81 1245.25,674.81 1245.25,671.95 1252.27,664.92 v1(1252.27,662.29)
NRST: P10.4 R37.2 U6.7 | length 866.3
  Top Layer w8: v1(1207.24,460.75) v1@1207.28,460.79 ; v1@1210.64,458.02 1208.75,456.12 U6.7@1208.75,408.19 1210.65,406.29 1210.65,377.39 1224.67,363.37 1286.63,363.37 1306.25,343.75 R37.2@1306.25,319.69
  Bottom Layer w8: P10.4@675,293.75 675,375 762.5,462.5 1205.5,462.5 v1(1207.24,460.75)
OC_ADJ: J1.1 U6.20 | length 712.4
  Top Layer w8: v1(1148.03,975.23) 1148.03,976.03 1159.95,987.96 1161.92,987.96 J1.1@1168.75,994.78 ; v1(1228.98,639) 1228.98,583.52 1257.89,554.61 1364.38,554.61 1372.99,545.99 U6.20@1464.66,545.99
  Bottom Layer w8: v1(1148.03,975.23) 1148.03,956.38 1142.25,950.6 1142.25,858.01 1165.23,835.03 1165.23,735.03 1231.25,669.01 1231.25,655.85 1230.84,655.44 1230.84,640.85 v1(1228.98,639)
OSC_IN: U6.5 X1.1 | length 111.3
  Top Layer w8: X1.1@1161.76,300 1161.76,356.66 1169.38,364.27 U6.5@1169.38,408.19
OSC_OUT: U6.6 X1.3 | length 150.8
  Top Layer w8: U6.6@1189.07,408.19 1190.97,406.29 1190.97,371.53 1213.13,349.37 1238.38,349.37 1256.25,331.5 X1.3@1256.25,300
PV_SENSE: C31.2 D2.1 R12.2 R13.1 U6.17 | length 1489
  Top Layer w8: v1(468.75,512.5) 650.5,512.5 656.75,506.25 v1(659.38,506.25) ; v1(1087.5,575) 1168.75,493.75 1317.11,493.75 v1(1318.47,492.39) ; v1(1406.25,487.5) 1406.53,487.22 1464.37,487.22 U6.17@1464.66,486.93
  Bottom Layer w8: R12.2@425.84,865.65 R13.1@425.84,790.65 425.84,758.96 431.81,753 431.81,740.24 C31.2@437.65,734.4 437.65,699.46 416.34,678.15 D2.1@406.5,678.15 406.5,537.25 431.25,512.5 v1(468.75,512.5) ; v1(659.38,506.25) 706.25,506.25 734.5,534.5 1028.25,534.5 1066.89,573.14 1085.64,573.14 v1(1087.5,575) ; v1(1318.47,492.39) 1319.83,493.75 1397.37,493.75 1403.62,487.5 v1(1406.25,487.5)
PVDD: C4.1 C5.1 C15.1 C16.1 C19.2 C20.2 C21.2 C22.2 C23.2 C24.2 C25.2 C26.2 C27.2 C28.2 C33.1 C34.1 C35.1 P1.1 P2.1 Q1.5 Q1.6 Q1.7 Q1.8 Q1.EXT Q2.5 Q2.6 Q2.7 Q2.8 Q2.EXT Q3.5 Q3.6 Q3.7 Q3.8 Q3.EXT R12.1 U1.29 U1.53 U1.54 | length 1891.6
  Top Layer w10: C4.1@1015.21,1478.1 1017.8,1475.51 1028.91,1475.51 1048.62,1455.79 U1.54@1048.62,1403.89 U1.53@1068.31,1403.89 ; U1.29@1540.75,1403.89 1541.65,1404.79 1541.65,1487.96 C16.1@1547.44,1493.75 C16.1@1548.44,1494.75
  Top Layer w24: P1.1@581.25,1545.32 664.39,1628.46 952.79,1628.46 981.25,1600 981.25,1571.26 1015.2,1537.31 1017.16,1537.31 1018.16,1536.31 C5.1@1018.16,1534.35 ; C4.1@1015.21,1478.1 1015.21,1529.44 C5.1@1018.16,1532.39 ; C16.1@1548.44,1494.75 1548.44,1548.05 C15.1@1550.39,1550
  Bottom Layer w24: R12.1@484.89,865.65 485.37,866.12 485.37,966.08 C23.2@485.84,966.56
  Bottom Layer w40: C21.2@485.68,1712.5 485.76,1712.42 C26.2@485.76,1550 ; C23.2@485.84,966.56 C23.2@485.84,966.56 485.76,1000 ; P2.1@581.25,1007.82 573.43,1000 485.76,1000 ; P1.1@581.25,1545.32 579.72,1546.85 488.91,1546.85 C26.2@485.76,1550 ; 485.76,1000 C26.2@485.76,1550
SH_A: C7.2 P3.X Q1.1 Q1.2 Q1.3 Q4.5 Q4.6 Q4.7 Q4.8 Q4.EXT R17.2 U1.46 | length 1124
  Top Layer w10: R17.2@884.35,1817.47 922.08,1817.47 927.05,1812.5 v1(929.14,1812.5) ; C7.2@1200,1562.11 1205.86,1556.25 v1(1228.19,1556.25) ; U1.46@1206.1,1403.89 v1(1206.1,1444.11)
  Bottom Layer w10: Q4.EXT@806.25,2030.46 855.85,1980.86 912.5,1980.86 928.14,1965.22 928.14,1813.5 v1(929.14,1812.5) 929.14,1810.41 934.36,1805.2 934.36,1690.64 971.81,1653.19 1097.03,1653.19 1148.34,1704.5 1193.35,1704.5 1227.64,1670.21 1227.64,1556.8 v1(1228.19,1556.25) ; v1(1206.1,1444.11) 1204.63,1445.59 1204.63,1450.96 1204.43,1451.16 1204.43,1479.32 1229.67,1504.55 v1@1229.67,1554.77
  other v2: 731.25,2181.25 768.75,2181.25 806.25,2181.25 843.75,2181.25 881.25,2181.25 731.25,2212.5 768.75,2212.5 806.25,2212.5 843.75,2212.5 881.25,2212.5 731.25,2243.75 768.75,2243.75 806.25,2243.75 843.75,2243.75 881.25,2243.75 731.25,2275 768.75,2275 806.25,2275 843.75,2275 881.25,2275 731.25,2306.25 768.75,2306.25 806.25,2306.25 843.75,2306.25 881.25,2306.25
SH_B: C9.2 P4.X Q2.1 Q2.2 Q2.3 Q5.5 Q5.6 Q5.7 Q5.8 Q5.EXT R18.2 U1.41 | length 818.6
  Top Layer w10: R18.2@1156.25,1825.94 1156.72,1825.47 1212.03,1825.47 v1(1212.5,1825) ; U1.41@1304.53,1403.89 1304.53,1476.92 v1(1304.94,1477.33)
  Bottom Layer w10: Q5.EXT@1081.25,2030.46 1143.35,1968.36 1187.89,1968.36 1212.5,1943.75 v1(1212.5,1825) 1243.69,1793.81 1243.69,1742.85 1306.25,1680.29 1306.25,1575 1304.5,1575 v1(1290.13,1560.63) 1290.13,1492.15 v1(1304.94,1477.33) v1@1306.42,1478.81
  other v2: 1006.25,2181.25 1043.75,2181.25 1081.25,2181.25 1118.75,2181.25 1156.25,2181.25 1006.25,2212.5 1043.75,2212.5 1081.25,2212.5 1118.75,2212.5 1156.25,2212.5 1006.25,2243.75 1043.75,2243.75 1081.25,2243.75 1118.75,2243.75 1156.25,2243.75 1006.25,2275 1043.75,2275 1081.25,2275 1118.75,2275 1156.25,2275 1006.25,2306.25 1043.75,2306.25 1081.25,2306.25 1118.75,2306.25 1156.25,2306.25
SH_C: C12.2 P5.X Q3.1 Q3.2 Q3.3 Q6.5 Q6.6 Q6.7 Q6.8 Q6.EXT R19.2 U1.36 | length 906.9
  Top Layer w10: v1(1362.5,1562.11) C12.2@1362.89,1562.5 ; v1(1401.78,1468.78) 1402.37,1468.19 1402.37,1404.47 U1.36@1402.95,1403.89 ; R19.2@1431.72,1825.47 R19.2@1431.25,1825.94 1474.06,1825.94 1475,1825 ; v1(1475,1662.5) 1475,1825 ; v1(1475,1843.75) 1475,1825
  Bottom Layer w10: v1(1362.5,1562.11) 1364.59,1562.11 1371.13,1555.57 1404.72,1555.57 ; v1(1401.78,1468.78) 1401.78,1552.62 1404.72,1555.57 ; Q6.EXT@1412.89,1974.61 Q6.EXT@1356.25,2031.25 1421.65,1965.85 1442.36,1965.85 1475,1933.21 v1(1475,1843.75) ; v1(1475,1662.5) 1473.83,1661.33 1473.83,1595.63 1433.77,1555.57 1404.72,1555.57
  other v2: 1250,2181.25 1287.5,2181.25 1325,2181.25 1362.5,2181.25 1400,2181.25 1250,2212.5 1287.5,2212.5 1325,2212.5 1362.5,2212.5 1400,2212.5 1250,2243.75 1287.5,2243.75 1325,2243.75 1362.5,2243.75 1400,2243.75 1250,2275 1287.5,2275 1325,2275 1362.5,2275 1400,2275 1250,2306.25 1287.5,2306.25 1325,2306.25 1362.5,2306.25
SL_A: Q4.1 Q4.2 Q4.3 R23.1 U1.33 U1.44 | length 1182.4
  Top Layer w8: v1(855.92,1698.3) 887.75,1666.46 1059.58,1666.46 1119.27,1606.78 1170.5,1606.78 ; 1170.53,1606.81 1249.78,1606.81 ; U1.44@1245.47,1403.89 1245.47,1446.67 1245.15,1447 1245.15,1474.22 1263.05,1492.11 1263.05,1573.23 1249.78,1586.49 1249.78,1606.85 1260.83,1617.9 1296.57,1617.9 1296.65,1617.82 1357.69,1617.82 1367.08,1627.21 1401.59,1627.21 1462.01,1566.8 U1.33@1462.01,1403.89
  Bottom Layer w8: R23.1@837.5,1815.8 856.87,1796.43 856.87,1699.25 v1(855.92,1698.3)
SL_B: Q5.1 Q5.2 Q5.3 R24.1 U1.31 U1.39 | length 1111.9
  Top Layer w8: v1(1066.15,1703.05) 1134.42,1634.78 1158.9,1634.78 ; 1158.93,1634.81 1238.14,1634.81 1253.33,1650 1327.43,1650 v1(1328.11,1650.68) ; v1@1328.6,1650.19 1329.08,1650.68 1350.95,1650.68 1357.81,1657.55 1410.86,1657.55 1495.69,1572.71 1495.69,1453.26 1501.38,1447.57 U1.31@1501.38,1403.89 ; v1(1343.75,1456.25) 1343.9,1456.1 U1.39@1343.9,1403.89
  Bottom Layer w8: v1@1066.15,1703.28 1066.15,1791.25 1090.69,1815.8 R24.1@1112.5,1815.8 ; v1(1328.11,1650.68) 1327.64,1650.21 1327.64,1472.36 v1(1343.75,1456.25)
  Bottom Layer w10: R24.1@1112.5,1815.8 R24.1@1152.85,1815.8
SO1: C17.1 R9.2 U6.26 | length 447.7
  Top Layer w8: U6.26@1464.66,664.1 1423.4,664.1 1406.25,681.25 1406.25,787.5 1430.03,811.28 1459.04,811.28 1495.73,847.96 1495.73,942.77 1475.88,962.62 C17.1@1474.9,962.62 R9.2@1474.9,1000.21
SO2: C18.1 R10.2 U6.27 | length 439.2
  Top Layer w8: U6.27@1464.66,683.78 1540.03,683.78 1568.86,712.61 1568.86,803.1 1568.75,803.21 1568.75,937.5 1543.63,962.62 C18.1@1518.65,962.62 R10.2@1518.65,1000.21
SPI_CS: U3.1 U6.50 | length 444.7
  Top Layer w8: v1(973.47,762.61) v1(973.47,762.61) 1011.85,762.57 U6.50@1011.9,762.52
  Bottom Layer w8: v1(973.47,762.61) 973.47,932.78 945.25,961 945.25,1055.65 980.62,1091.02 991.02,1091.02 1000.85,1100.85 1000.85,1126.48 U3.1@1001.97,1127.6
SPI_MISO: U3.3 U6.56 | length 572.8
  Top Layer w8: v1(932.08,761.67) 933.11,760.64 933.11,749.81 937.61,745.31 937.61,674.89 966.18,646.32 1009.99,646.32 U6.56@1011.9,644.41
  Bottom Layer w8: v1(932.08,761.67) 932.08,764.29 940.61,772.82 940.61,777.06 945.25,781.7 945.25,909.14 917.25,937.14 917.25,1067.25 949.67,1099.67 949.67,1126.48 U3.3@950.79,1127.6
SPI_MOSI: U3.4 U6.57 | length 614.1
  Top Layer w8: v1(918.75,737.5) 918.75,701.92 912.39,695.56 912.39,662.61 950.27,624.73 U6.57@1011.9,624.73
  Bottom Layer w8: v1(918.75,737.5) 918.75,740.13 912.39,746.49 912.39,768.64 931.25,787.5 931.25,903.34 912.63,921.96 912.39,921.96 903.25,931.1 903.25,1073.05 925.2,1095 U3.4@925.2,1127.6
SPI_SCK: U3.2 U6.55 | length 542.2
  Top Layer w8: v1(956.47,743.75) 958.33,741.89 958.33,724.63 964.07,718.89 964.07,673.43 971.49,666.01 1009.99,666.01 U6.55@1011.9,664.1
  Bottom Layer w8: v1(956.47,743.75) 954.61,745.61 954.61,771.26 959.25,775.9 959.25,922 931.25,950 931.25,1061.45 974.82,1105.02 975.26,1105.02 976.38,1106.14 U3.2@976.38,1127.6
SWCLK: P10.1 U6.49 | length 1283.6
  Top Layer w8: U6.49@1011.9,782.21 1012.38,781.73 1105.77,781.73 v1(1106.25,781.25)
  Bottom Layer w8: P10.1@375,293.75 500,418.75 678.15,418.75 751.9,492.5 1130,492.5 1193.86,556.36 1193.86,666.8 1106.25,754.41 v1(1106.25,781.25)
SWDIO: P10.3 U6.46 | length 1089.2
  Top Layer w8: U6.46@1130.01,860.95 1130.42,860.54 1130.42,812.92 v1(1130.84,812.5)
  Bottom Layer w8: P10.3@575,293.75 661,379.75 661,380.8 756.7,476.5 1145.25,476.5 1207.86,539.11 1207.86,672.6 1130.84,749.62 v1(1130.84,812.5)
UART1_RX: P9.3 U6.59 | length 998.9
  Top Layer w8: P9.3@333.81,690.55 328.31,685.05 291.3,685.05 282.5,676.25 282.5,636.25 351.5,567.25 470.22,567.25 485.47,582.5 664.8,582.5 801.9,719.61 853.26,719.61 864.98,707.88 864.98,665.22 943.97,586.23 1011.03,586.23 U6.59@1011.9,585.36
UART1_TX: P9.4 U6.58 | length 871
  Top Layer w8: P9.4@333.81,651.18 331.25,648.62 331.25,618.75 368.75,581.25 464.42,581.25 479.67,596.5 659,596.5 796.11,733.61 859.06,733.61 878.98,713.68 878.98,671.02 944.96,605.04 U6.58@1011.9,605.04
USB_N: R36.1 U6.44 | length 617.2
  Top Layer w8: R36.1@860.14,562.6 871.33,573.8 v1(871.33,606.14) ; v1(1087.5,625) 1087.5,627.63 1082.64,632.49 1082.64,695.14 1158.33,770.83 1166.54,779.04 1166.54,826.37 1167.47,827.31 1167.47,859.05 U6.44@1169.38,860.95
  Bottom Layer w8: v1(871.33,606.14) 871.33,603.51 876.19,598.65 876.19,572.76 892.25,556.7 900.45,548.5 1022.45,548.5 1071.82,597.87 1085.64,611.69 1085.64,623.14 v1(1087.5,625)
USB_P: R35.1 U6.45 | length 566
  Top Layer w8: v1(895.05,606.14) 895.05,574.63 R35.1@906.25,563.43 ; v1(1063.78,625) 1063.78,627.63 1068.64,632.49 1068.64,700.94 1152.54,784.83 1152.54,826.37 1151.6,827.31 1151.6,859.05 U6.45@1149.7,860.95
  Bottom Layer w8: v1(895.05,606.14) 895.05,603.51 890.19,598.65 890.19,578.56 906.25,562.5 1016.65,562.5 1061.92,607.77 1061.92,623.14 v1(1063.78,625)
VBUS: D12.2 U5.5 USB1.2 USB1.11 | length 543.4
  Top Layer w20: v1@830.12,362.5 809.59,383.03 796.79,383.03 762.5,417.32 D12.2@762.5,430.12 874.65,430.12 900,455.47 U5.5@900,476.53 ; USB1.2@830.71,320.96 831.25,321.5 v1(831.25,362.5) ; v1(1018.75,362.5) 1018.75,321.9 USB1.11@1019.69,320.96
  Bottom Layer w20: v1(831.25,362.5) v1(1018.75,362.5)
pads on no net: P1.3 P1.4 P2.3 P2.4 P6.X P7.X P8.X P9.X U1.4 U1.55 U3.6 U3.7 U3.8 U3.9 U3.10 U3.14 U4.5 U6.1 U6.3 U6.4 U6.11 U6.23 U6.24 U6.25 U6.28 U6.29 U6.30 U6.51 U6.52 U6.53 U6.54 USB1.3 USB1.4 USB1.9 USB1.10 USB1.MH1 USB1.MH2

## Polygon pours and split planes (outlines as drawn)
GND on Bottom Layer "GNDA" (solid, remove dead copper, pour order 7): 681.25,931.25 681.25,1437.5 1025,1437.5 1025,1306.25 1712.5,1306.25 1712.5,2425 137.5,2425 137.5,931.25
GND on Bottom Layer "GND" (solid, remove dead copper, pour order 6): 137.5,918.75 693.75,918.75 693.75,1425 818.75,1425 1012.9,1425 1012.07,1294.5 1712.5,1292.94 1712.5,62.5 137.5,62.5
SH_A on Bottom Layer "SH_A" (solid, remove dead copper, pour order 1): 712.5,1956.25 712.5,2325 900,2325 900,1956.25
SH_C on Bottom Layer "SH_C" (solid, remove dead copper, pour order 3): 1231.25,1956.25 1231.25,2325 1450,2325 1450,1956.25
SH_B on Bottom Layer "SH_B" (solid, remove dead copper, pour order 2): 987.5,1956.25 987.5,2325 1178.12,2325 1178.12,1956.25
SL_B on Bottom Layer "SL_B" (solid, remove dead copper, pour order 5): 1040.42,1927.92 1040.42,1784.17 1190.42,1784.17 1190.42,1927.92
SL_A on Bottom Layer "SL_A" (solid, remove dead copper, pour order 4): 762.5,1925 762.5,1781.25 912.5,1781.25 912.5,1925
PVDD on Top Layer "PVDD" (solid, remove dead copper, pour order 10): 450,1462.5 450,2056.25 1456.25,2056.25 1456.25,1918.75 1568.75,1918.75 1568.75,1443.75 1525,1443.75 1525,1531.25 1525,1856.25 687.5,1856.25 687.5,1462.5
SH_A on Top Layer "SH_A" (solid, remove dead copper, pour order 0): 712.5,2325 900,2325 900,2087.5 712.5,2087.5
SH_C on Top Layer "SH_C" (solid, remove dead copper, pour order 9): 1231.25,2325 1446.88,2325 1446.88,2087.5 1231.25,2087.5
SH_B on Top Layer "SH_B" (solid, remove dead copper, pour order 8): 987.5,2325 1178.12,2325 1178.12,2087.5 987.5,2087.5

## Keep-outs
Keep-Out Layer:
  the board outline again, w3.94

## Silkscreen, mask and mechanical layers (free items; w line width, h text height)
Top Overlay:
  text "HAL/ENCD" at 366.57,2241.99 h60
  text "CLK" at 353.09,209.49 h60
  text "GND" at 437.02,209.49 h60
  text "DIO" at 546.95,209.49 h60
  text "RST" at 646.9,209.49 h60
Bottom Overlay:
  text "CAN" at 233.68,1503.24 h60
  text "CAN" at 227.43,959.49 h60
Top Solder:
  lines w50: 581.25,1545.32 487.5,1639.07 487.5,1781.25 681.25,1975 1406.25,1975
Mechanical 1:
  circle w3.94: c236.22,2013.03 r59.06
  circle w3.94: c236.22,2013.03 r98.43
  circle w3.94: c1614.17,2013.03 r98.43
  circle w3.94: c1614.17,2013.03 r59.06
  circle w3.94: c1614.17,472.44 r98.43
  circle w3.94: c1614.17,472.44 r59.06
  circle w3.94: c236.22,472.44 r59.06
  circle w3.94: c236.22,472.44 r98.43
